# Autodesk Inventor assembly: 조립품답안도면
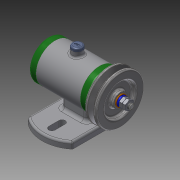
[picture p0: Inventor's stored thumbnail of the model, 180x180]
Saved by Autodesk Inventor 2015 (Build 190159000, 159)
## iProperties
Created: 2017-12
Part Number: 조립품답안도면
Document SubType Name: Assembly
Designer: 2-PC10
Author: 2-PC10
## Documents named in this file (14)
- C:\Users\2-PC10\Desktop\471207V1019\조립품답안도면.iam
- C:\Users\2-PC10\Desktop\471207V1019\본체.ipt
- C:\Users\2-PC10\Desktop\471207V1019\베어링 15 x 32 x 9.ipt
- C:\Users\2-PC10\Desktop\471207V1019\뒤커버.ipt
- C:\Users\2-PC10\Desktop\471207V1019\앞커버.ipt
- C:\Users\2-PC10\Desktop\471207V1019\볼트 M4 x 12.ipt
- C:\Users\2-PC10\Desktop\471207V1019\오일 실 15 25 7.ipt
- C:\Users\2-PC10\Desktop\471207V1019\축.ipt
- C:\Users\2-PC10\Desktop\471207V1019\키 3 x 3 x 12.ipt
- C:\Users\2-PC10\Desktop\471207V1019\V벨트풀리.ipt
- C:\Users\2-PC10\Desktop\471207V1019\와셔 8x17.ipt
- C:\Users\2-PC10\Desktop\471207V1019\스프링와셔 8.ipt
- C:\Users\2-PC10\Desktop\471207V1019\너트 M 8.ipt
- C:\Users\2-PC10\Desktop\471207V1019\고무캡.ipt
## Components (2 placed, 2 different names)
1. V벨트풀리:1 — 각도:1
2. 고무캡:1 — 각도:4
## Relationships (2: Angle 2)
- 각도:1 [Angle]: V벨트풀리:1
- 각도:4 [Angle]: 고무캡:1
